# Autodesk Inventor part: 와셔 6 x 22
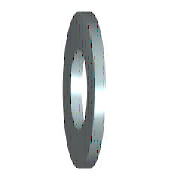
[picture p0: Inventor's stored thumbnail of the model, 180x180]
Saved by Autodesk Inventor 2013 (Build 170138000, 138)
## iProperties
Created: 2012-02
Part Number: 와셔 6 x 22
Material: 강철
Description: 평면 와셔 - 초대형 시리즈 - 제품 등급 C
Document SubType Name: Modeling
Standard: ISO 7094
Designer: mdu-01
Standard Revision: Second edition 2000-06-01
Standards Organization: ISO
Language: ko-KR
Size Designation: ST 6 - 100 HV
Categories: <MemberInstance><Categories><Category DisplayName="조임쇠" InternalName="e4da775c-781d-43d5-af7c-5136215cf5a6" Mnemonic="FSTN"><Category DisplayName="와셔" InternalN
Density: 7.85 g/cm^3
IsCustomPart: 1
Author: mdu-01
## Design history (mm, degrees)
sketch "스케치"
  geometry: C1 r 11 at (0, 0); C2 r 3.3 at (0, 0); 1 further point
  constraints: 2 centre point, 2 coincident
  dimensions: "d0" = 6.6 diameter of C2 (= SD1); "d1" = 22 diameter of C1 (= SD2)
extrude "본체" new body sketch "스케치" distance "d2" = 2 (= SD); taper "d3" = 0 deg
workaxis "Work Axis1"
workplane "Work Plane1"
body "Solid1"
other parameters: "SD1" = 6.6 [user parameter; used in 1 equation term], "SD2" = 22 [user parameter; used in 1 equation term], "SD" = 2 [user parameter; used in 1 equation term], "d4" = 0, "d5" = 0, "d6" = 0, "d7" = 0, "NND" = 6 [user parameter]
